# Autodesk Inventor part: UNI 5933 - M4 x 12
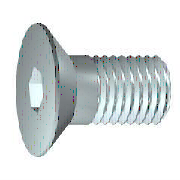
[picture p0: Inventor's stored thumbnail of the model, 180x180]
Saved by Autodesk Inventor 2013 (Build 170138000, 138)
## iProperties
Created: 2007-03
Part Number: UNI 5933 - M4 x 12
Material: Steel, Mild
Description: Countersunk Screw
Document SubType Name: Modeling
Standard: UNI 5933
Designer: Autodesk, Inc.
Standards Organization: UNI
Language: en-US
Size Designation: M4 x 12
Categories: <MemberInstance><Categories><Category DisplayName="Fasteners" InternalName="e4da775c-781d-43d5-af7c-5136215cf5a6" Mnemonic="FSTN"><Category DisplayName="Bolts"
Density: 7.86 g/cm^3
Mass: 1.43572 g
Surface Area: 2.50381 cm^2
Volume: 0.182661 cm^3
IsCustomPart: 0
Author: Autodesk, Inc.
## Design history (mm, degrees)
body "Solid1"
revolve "Body" stored, may be unused: angle "d13" = 90 deg
sketch "Sketch2"
  geometry: L1 (0, -5.348)-(0, 5.348) reference; L2 (-5.348, 0)-(5.348, 0) reference; L3 (1.443, 0)-(0.722, -1.25); L4 (0.722, -1.25)-(-0.722, -1.25); L5 (-0.722, -1.25)-(-1.443, 0); L6 (-1.443, 0)-(-0.722, 1.25); L7 (-0.722, 1.25)-(0.722, 1.25); L8 (0.722, 1.25)-(1.443, 0); A1 r 1.443 centre (0, 0) between (0, 1.443) and (1.443, 0) reference; 2 further points
  constraints: 12 end point, 2 coincident, 2 point on circle, 2 point on line, 12 other
extrude "Slot" join sketch "Sketch2" taper "d14" = 0 deg; stored distance "d30" = 10
feature "Thread" dims "d15" = 7.95 (= GEL), "d16" = 0
chamfer "Chamfer1" distance "d17" = 0.42941 (= -0.5 x SPD + 0.5 x GD); stored, may be unused: second distance "d18" = 0.42941 (= GUL), angle "d39" = 45 deg
workplane "Work Plane1"
sketch "Sketch1"
  geometry: L1 (12, 0)-(12, 2); L2 (12, 2)-(4.05, 2); L3 (4.05, 2)-(3.621, 2); L4 (0, 3.82)-(0, 1.443); L5 (0, 1.443)-(1.55, 1.443); L6 (1.55, 1.443)-(2.383, 0); L7 (2.383, 0)-(12, 0); L8 (0, 3.82)-(0.48, 3.82); L9 (0.48, 3.82)-(2.3, 2); L10 (3.621, 2)-(2.3, 2); L11 (4.05, 2)-(2.3, 2); L12 (2.3, 2)-(2.3, 2); L13 (-2.4, 0)-(14.4, 0) reference; L14 (0, -0.764)-(0, 4.584) reference
  constraints: 24 end point, 4 collinear, 3 parallel
  dimensions: "d0" = 12 distance between parallel lines of L4 L1 (= NLG); "d1" = 7.95 distance from line of L2.end L1 (= GEL); "d2" = 1.55 distance from line of L5.end L4 (= INTI); "d3" = 4 diameter of L2 L7 (= GD); "d6" = 2.3 distance from line of L9.end L4 (= KOH); "d7" = 45 deg angle of L9 L7 (= 0.5 x SEWI); "d8" = 2.88675 diameter of L5 L7 (= 1.1547 x SW); "d9" = 60 deg angle of L6 L7; "d10" = 7.64 diameter of L8 L7 (= KOD); "d11" = 4 diameter of L10 L7 (= BDM); "d12" = 0.42941 distance of L3.end L2.end (= GAL)
other parameters: "NLG" = 12 [user parameter; used in 1 equation term], "INTI" = 1.55 [user parameter; used in 1 equation term], "GEL" = 7.95 [user parameter; used in 2 equation terms], "GAL" = 0.42941 (= 0.61345 x PTC) [user parameter; used in 1 equation term], "KOH" = 2.3 [user parameter; used in 1 equation term], "KOD" = 7.64 [user parameter; used in 1 equation term], "GUL" = 0.42941 (= 0.61345 x PTC) [user parameter; used in 1 equation term], "SPD" = 3.14117 (= NND - 1.2269 x PTC) [user parameter; used in 1 equation term], "BDM" = 4 (= NND) [user parameter; used in 1 equation term], "GD" = 4 (= NND) [user parameter; used in 2 equation terms], "SEWI" = 90 deg [user parameter; used in 1 equation term], "d20" = 0, "SW" = 2.5 [user parameter; used in 2 equation terms], "d43" = 0, "d44" = 0, "TOA" = 30 deg [user parameter], "GD1" = 3.14117 (= THREADDIA - 1.2269 x PTC) [user parameter], "EPV" = 4.3 [user parameter], "THREADDIA" = 4 [user parameter; used in 1 equation term], "TPU" = 14.28571 (computed from PTC) [user parameter], "PTC" = 0.7 [user parameter; used in 5 equation terms], "NND" = 4 [user parameter; used in 3 equation terms], "E0" = 2.8875 (= 1.155 x SW) [user parameter]
